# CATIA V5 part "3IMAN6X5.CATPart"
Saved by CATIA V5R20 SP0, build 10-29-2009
Part number: 3IMAN6X5
Revision: ANY
Definition: UNKNOWN
Nomenclature: 3IMAN6X5
Source: Unknown
Bounding box of the stored display mesh (mm): x -2.853 to 2.853, y 0 to 5, z -3 to 3
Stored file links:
  C:\Users\Utente\Desktop\IO LAVORO\3D X SITO CF\CUMSA\3D files CC\CCHS5328\3IMAN6X5.CATPart
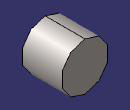
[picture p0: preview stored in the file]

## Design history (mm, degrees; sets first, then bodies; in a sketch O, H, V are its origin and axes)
Body1 "Saliente-Extruir1" (main body)
  Solid1: solid without history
